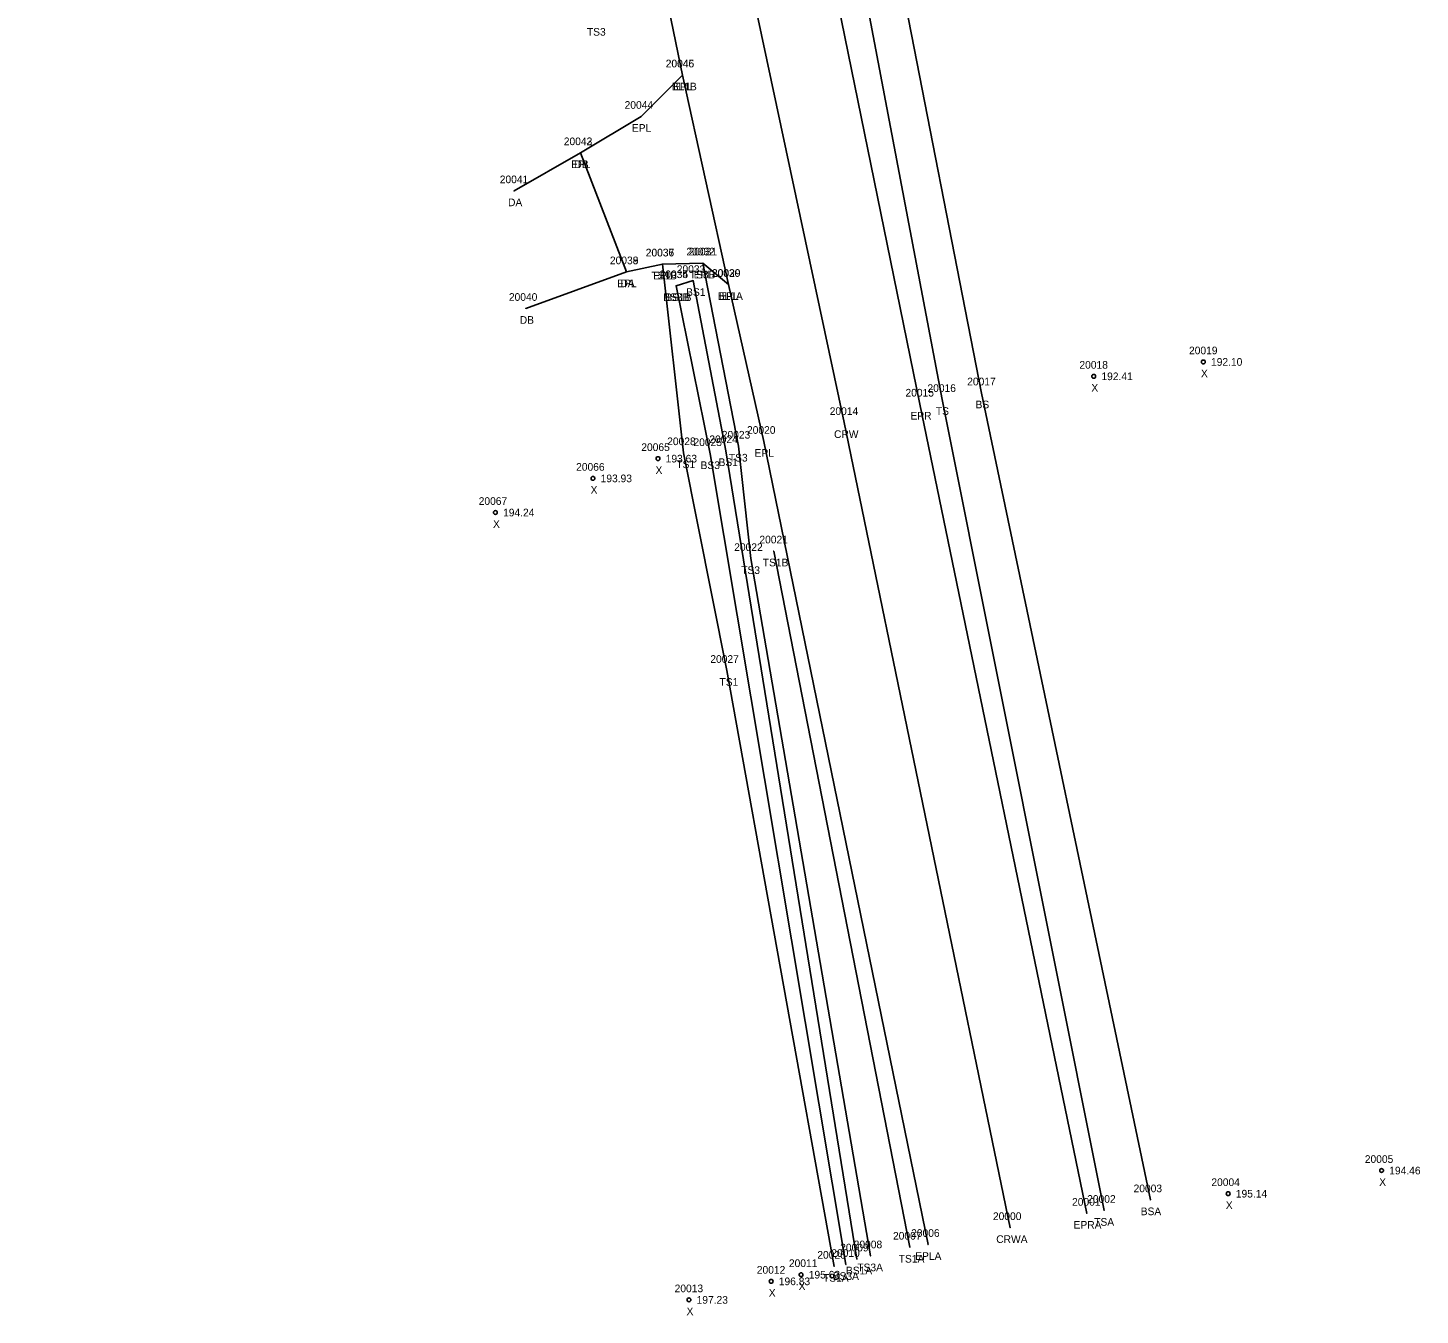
# Model space of a CAD drawing. Extents: x 2077883 to 2078272, y 787819 to 788945.
# Drawn here: x 2078090.2 to 2078272, y 787819 to 787987.1 of the extents above; entities that cross this region are included whole.
import ezdxf

# ---------------------------------------------------------------- set-up
doc = ezdxf.new("R2010")
doc.units = 0
for name, color, linetype in [('RD_DTM_BkLn1', 7, 'Continuous'), ('RD_DTM_BkLn2', 7, 'Continuous'), ('RD_EX_Driveway', 7, 'Continuous'), ('RD_EX_Driveway_txCode', 7, 'Continuous'), ('RD_EX_Road', 7, 'Continuous'), ('RD_EX_Road_txCode', 7, 'Continuous'), ('RD_Sketch8', 7, 'Continuous'), ('RD_SMD_Locator', 7, 'Continuous'), ('RD_SMD_Misc', 7, 'Continuous')]:
    doc.layers.add(name, color=color, linetype=linetype)

msp = doc.modelspace()

# ---------------------------------------------------------------- linework, layer by layer
at = {"layer": 'RD_DTM_BkLn1'}
msp.add_line((2078181.72, 787953.57), (2078175.69, 787980.93), dxfattribs=at)
msp.add_lwpolyline([(2078218.47, 787830.39), (2078196.8, 787935.53), (2078175.25, 788036.87), (2078153.19, 788138.02), (2078130.35, 788242.05), (2078107.99, 788344.95), (2078104.08, 788361.32)], dxfattribs=at)
at = {"layer": 'RD_DTM_BkLn2'}
msp.add_line((2078205.39, 787827.83), (2078187.62, 787918.76), dxfattribs=at)
for points in [[(2078230.74, 787832.64), (2078209.59, 787938.54), (2078198.68, 787996.21)], [(2078236.8, 787834.02), (2078214.75, 787939.4), (2078203.81, 787995.39)], [(2078195.49, 787825.34), (2078181.5, 787903.16), (2078175.86, 787931.59), (2078173.08, 787956.24)], [(2078200.26, 787826.7), (2078184.62, 787917.77), (2078183, 787932.45), (2078178.38, 787956.37)], [(2078198.49, 787826.29), (2078181.37, 787931.86), (2078177.12, 787954.08), (2078174.88, 787953.41)], [(2078197.04, 787825.57), (2078179.3, 787931.47), (2078174.88, 787953.41)]]:
    msp.add_lwpolyline(points, dxfattribs=at)
at = {"layer": 'RD_EX_Driveway'}
for p, q in [((2078153.72, 787965.8), (2078162.37, 787970.77)), ((2078168.39, 787955.22), (2078155.24, 787950.44))]:
    msp.add_line(p, q, dxfattribs=at)
at = {"layer": 'RD_EX_Road'}
for points in [[(2078228.48, 787832.26), (2078206.7, 787937.94), (2078195.2, 787994.28), (2078202.14, 788002.84), (2078209.52, 788006.82), (2078218.3, 788009.13), (2078214.45, 788022.16), (2078205.73, 788019.64), (2078196.71, 788020.24), (2078189.11, 788024.39), (2078185.07, 788039.81), (2078163.11, 788140.18), (2078140.34, 788243.77), (2078121.8, 788330.62), (2078118.87, 788349.48), (2078108.52, 788359.43), (2078104.08, 788361.32), (2078095.01, 788364.85), (2078090.24, 788364.37)], [(2078207.78, 787828.19), (2078186.33, 787933.07), (2078181.72, 787953.57), (2078178.38, 787956.37), (2078173.08, 787956.24), (2078168.39, 787955.22), (2078162.37, 787970.77), (2078170.31, 787975.52), (2078175.69, 787980.93), (2078164.7, 788034.41), (2078142.62, 788135.61), (2078141.74, 788139.37), (2078130.94, 788148.94), (2078127.54, 788150.51), (2078123.47, 788152.38), (2078119.52, 788165.5), (2078134.14, 788173.23), (2078127.9, 788201.23), (2078119.52, 788239.75), (2078097, 788341.89), (2078090.24, 788364.37)]]:
    msp.add_lwpolyline(points, dxfattribs=at)
at = {"layer": 'RD_SMD_Locator'}
for centre, radius in [((2078175.69, 787980.93), 0.001), ((2078175.69, 787980.93), 0.001), ((2078170.31, 787975.52), 0.001), ((2078162.37, 787970.77), 0.001), ((2078162.37, 787970.77), 0.001), ((2078153.72, 787965.8), 0.001), ((2078168.39, 787955.22), 0.001), ((2078168.39, 787955.22), 0.001), ((2078173.08, 787956.24), 0.001), ((2078173.08, 787956.24), 0.001), ((2078178.38, 787956.37), 0.001), ((2078178.38, 787956.37), 0.001), ((2078174.88, 787953.41), 0.001), ((2078174.88, 787953.41), 0.001), ((2078177.12, 787954.08), 0.001), ((2078181.72, 787953.57), 0.001), ((2078181.72, 787953.57), 0.001), ((2078155.24, 787950.44), 0.001), ((2078243.71, 787943.46), 0.25), ((2078229.4, 787941.58), 0.25), ((2078209.59, 787938.54), 0.001), ((2078214.75, 787939.4), 0.001), ((2078206.7, 787937.94), 0.001), ((2078196.8, 787935.53), 0.001), ((2078186.33, 787933.07), 0.001), ((2078175.86, 787931.59), 0.001), ((2078179.3, 787931.47), 0.001), ((2078181.37, 787931.86), 0.001), ((2078183, 787932.45), 0.001), ((2078172.51, 787930.83), 0.25), ((2078164.02, 787928.25), 0.25), ((2078151.28, 787923.79), 0.25), ((2078187.62, 787918.76), 0.001), ((2078184.62, 787917.77), 0.001), ((2078181.5, 787903.16), 0.001), ((2078266.98, 787837.85), 0.25), ((2078246.95, 787834.83), 0.25), ((2078236.8, 787834.02), 0.001), ((2078228.48, 787832.26), 0.001), ((2078230.74, 787832.64), 0.001), ((2078218.47, 787830.39), 0.001), ((2078205.39, 787827.83), 0.001), ((2078207.78, 787828.19), 0.001), ((2078198.49, 787826.29), 0.001), ((2078200.26, 787826.7), 0.001), ((2078191.19, 787824.25), 0.25), ((2078195.49, 787825.34), 0.001), ((2078197.04, 787825.57), 0.001), ((2078187.28, 787823.38), 0.25), ((2078176.55, 787820.96), 0.25)]:
    msp.add_circle(centre, radius, dxfattribs=at)

# ---------------------------------------------------------------- texts
at = {"layer": 'RD_EX_Driveway_txCode'}
for s, p in [('20042', (2078160.21, 787971.77)), ('DB', (2078161.59, 787968.77)), ('20041', (2078151.85, 787966.8)), ('DA', (2078152.93, 787963.8)), ('20039', (2078166.23, 787956.22)), ('DA', (2078167.6, 787953.22)), ('20040', (2078153.04, 787951.44)), ('DB', (2078154.46, 787948.44))]:
    msp.add_text(s, height=1, dxfattribs=at).set_placement(p)
at = {"layer": 'RD_EX_Road_txCode'}
for s, p in [('20045', (2078173.53, 787981.93)), ('EPL', (2078174.49, 787978.93)), ('20044', (2078168.15, 787976.52)), ('EPL', (2078169.1, 787973.52)), ('20043', (2078160.21, 787971.77)), ('EPL', (2078161.16, 787968.77)), ('20038', (2078166.23, 787956.22)), ('20037', (2078170.92, 787957.24)), ('20032', (2078176.22, 787957.37)), ('EPL', (2078171.87, 787954.24)), ('EPL', (2078177.17, 787954.37)), ('20029', (2078179.57, 787954.57)), ('EPL', (2078167.19, 787953.22)), ('EPL', (2078180.52, 787951.57)), ('20015', (2078204.82, 787938.94)), ('EPR', (2078205.47, 787935.94)), ('20020', (2078184.13, 787934.07)), ('EPL', (2078185.12, 787931.07)), ('20001', (2078226.57, 787833.26)), ('EPRA', (2078226.77, 787830.26)), ('20006', (2078205.56, 787829.19)), ('EPLA', (2078206.09, 787826.19))]:
    msp.add_text(s, height=1, dxfattribs=at).set_placement(p)
at = {"layer": 'RD_Sketch8'}
for s, p in [('20019', (2078241.84, 787944.46)), ('192.10', (2078244.71, 787942.96)), ('20018', (2078227.53, 787942.58)), ('X', (2078243.4, 787941.46)), ('X', (2078229.09, 787939.58)), ('192.41', (2078230.4, 787941.08)), ('20065', (2078170.33, 787931.83)), ('193.63', (2078173.51, 787930.33)), ('20066', (2078161.82, 787929.25)), ('X', (2078172.19, 787928.83)), ('193.93', (2078165.02, 787927.75)), ('20067', (2078149.1, 787924.79)), ('X', (2078163.71, 787926.25)), ('194.24', (2078152.28, 787923.29)), ('X', (2078150.97, 787921.79)), ('20005', (2078264.79, 787838.85)), ('20004', (2078244.76, 787835.83)), ('X', (2078266.67, 787835.85)), ('194.46', (2078267.98, 787837.35)), ('195.14', (2078247.95, 787834.33)), ('X', (2078246.64, 787832.83)), ('20011', (2078189.6, 787825.25)), ('20012', (2078185.41, 787824.38)), ('195.63', (2078192.19, 787823.75)), ('20013', (2078174.68, 787821.96)), ('X', (2078186.97, 787821.38)), ('196.83', (2078188.28, 787822.88)), ('X', (2078190.87, 787822.25)), ('197.23', (2078177.55, 787820.46)), ('X', (2078176.24, 787818.96))]:
    msp.add_text(s, height=1, dxfattribs=at).set_placement(p)
at = {"layer": 'RD_SMD_Misc'}
for s, p in [('TS3', (2078163.23, 787986.07)), ('20046', (2078173.51, 787981.93)), ('BL1B', (2078174.3, 787978.93)), ('20036', (2078170.9, 787957.24)), ('20031', (2078176.5, 787957.37)), ('TS1B', (2078171.65, 787954.24)), ('20034', (2078172.72, 787954.41)), ('20035', (2078172.72, 787954.41)), ('20033', (2078174.96, 787955.08)), ('TS3B', (2078176.66, 787954.37)), ('20030', (2078179.53, 787954.57)), ('BS1', (2078176.18, 787952.08)), ('BS3B', (2078173.18, 787951.41)), ('BS1B', (2078173.46, 787951.41)), ('BL1A', (2078180.31, 787951.57)), ('20016', (2078207.69, 787939.54)), ('20017', (2078212.88, 787940.4)), ('20014', (2078194.93, 787936.53)), ('TS', (2078208.79, 787936.54)), ('BS', (2078213.97, 787937.4)), ('20028', (2078173.71, 787932.59)), ('20025', (2078177.14, 787932.47)), ('20024', (2078179.21, 787932.86)), ('20023', (2078180.84, 787933.45)), ('CRW', (2078195.49, 787933.53)), ('TS3', (2078181.76, 787930.45)), ('TS1', (2078174.9, 787929.59)), ('BS3', (2078178.07, 787929.47)), ('BS1', (2078180.42, 787929.86)), ('20021', (2078185.75, 787919.76)), ('20022', (2078182.46, 787918.77)), ('TS3', (2078183.37, 787915.77)), ('TS1B', (2078186.19, 787916.76)), ('20027', (2078179.34, 787904.16)), ('TS1', (2078180.54, 787901.16)), ('20003', (2078234.6, 787835.02)), ('20002', (2078228.54, 787833.64)), ('20000', (2078216.24, 787831.39)), ('TSA', (2078229.46, 787830.64)), ('BSA', (2078235.53, 787832.02)), ('20007', (2078203.19, 787828.83)), ('20009', (2078196.29, 787827.29)), ('20008', (2078198.06, 787827.7)), ('CRWA', (2078216.67, 787828.39)), ('20026', (2078193.31, 787826.34)), ('20010', (2078195.13, 787826.57)), ('TS1A', (2078203.94, 787825.83)), ('TS1A', (2078194.05, 787823.34)), ('BS3A', (2078195.32, 787823.57)), ('BS1A', (2078197.05, 787824.29)), ('TS3A', (2078198.53, 787824.7))]:
    msp.add_text(s, height=1, dxfattribs=at).set_placement(p)

doc.saveas('drawing.dxf')
